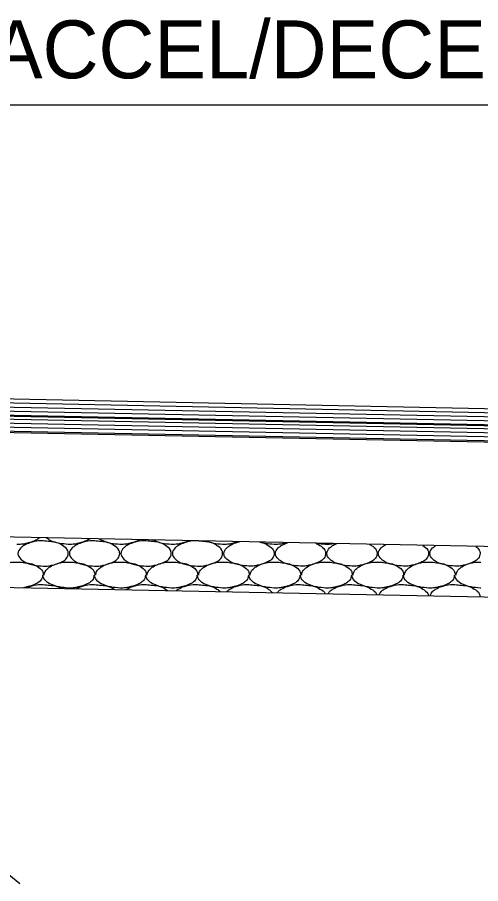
# Model space of a CAD drawing. Extents: x 1364961 to 1365294, y 367927 to 368034.
# Drawn here: x 1365220.25 to 1365224.86, y 367967.31 to 367975.93 of the extents above; entities that cross this region are included whole.
import ezdxf

# ---------------------------------------------------------------- set-up
doc = ezdxf.new("R2010")
doc.units = 0
doc.layers.add('Default', color=7, linetype='Continuous')

msp = doc.modelspace()

# ---------------------------------------------------------------- linework, layer by layer
at = {"layer": 'Default'}
for p, q in [((1365217.487, 367975.0585), (1365229.476, 367975.0585)), ((1365229.476, 367971.9458), (1365193.4981, 367972.6644)), ((1365229.476, 367971.9058), (1365193.4991, 367972.6244)), ((1365229.476, 367971.8657), (1365193.4991, 367972.5844)), ((1365229.476, 367971.7758), (1365193.2513, 367972.4993)), ((1365229.476, 367971.8257), (1365193.5011, 367972.5444)), ((1365229.476, 367971.7857), (1365193.5011, 367972.5044)), ((1365229.476, 367971.7456), (1365193.5021, 367972.4644)), ((1365229.476, 367971.7056), (1365193.5031, 367972.4244)), ((1365229.476, 367971.6126), (1365193.4981, 367972.3314)), ((1365229.476, 367971.6656), (1365193.5031, 367972.3844)), ((1365229.476, 367971.6256), (1365193.5051, 367972.3444)), ((1365232.8432, 367970.506), (1365217.471, 367970.8134)), ((1365220.2539, 367970.6874), (1365220.2479, 367970.6874)), ((1365220.7659, 367970.6874), (1365220.7599, 367970.6874)), ((1365221.2779, 367970.6874), (1365221.2719, 367970.6874)), ((1365221.7899, 367970.6874), (1365221.7839, 367970.6874)), ((1365222.3019, 367970.6874), (1365222.2959, 367970.6874)), ((1365222.8139, 367970.6874), (1365222.8079, 367970.6874)), ((1365223.3259, 367970.6874), (1365223.3199, 367970.6874)), ((1365247.5384, 367969.7092), (1365218.479, 367970.2901)), ((1365220.7659, 367970.2534), (1365220.7599, 367970.2534)), ((1365221.2779, 367970.2534), (1365221.2719, 367970.2534)), ((1365221.7899, 367970.2534), (1365221.7839, 367970.2534)), ((1365222.3019, 367970.2534), (1365222.2959, 367970.2534)), ((1365222.8139, 367970.2534), (1365222.8079, 367970.2534)), ((1365223.3259, 367970.2534), (1365223.3199, 367970.2534)), ((1365223.8379, 367970.2534), (1365223.8319, 367970.2534)), ((1365224.3499, 367970.2534), (1365224.3439, 367970.2534)), ((1365224.8619, 367970.2534), (1365224.8559, 367970.2534)), ((1365220.2803, 367967.3121), (1365218.1228, 367969.0246))]:
    msp.add_line(p, q, dxfattribs=at)
for points in [[(1365220.4769, 367970.7534), (1365220.4479, 367970.7334), (1365220.4079, 367970.7154), (1365220.3479, 367970.6974), (1365220.3099, 367970.6894), (1365220.2539, 367970.6874)], [(1365220.7599, 367970.6874), (1365220.6719, 367970.6974), (1365220.5699, 367970.7334), (1365220.5429, 367970.7524)], [(1365220.5099, 367970.4714), (1365220.4219, 367970.4814), (1365220.3199, 367970.5174), (1365220.2679, 367970.5674), (1365220.2599, 367970.5974), (1365220.2879, 367970.6514), (1365220.3179, 367970.6754), (1365220.3799, 367970.7034), (1365220.4659, 367970.7214), (1365220.5099, 367970.7214), (1365220.5759, 367970.7154), (1365220.6479, 367970.7034), (1365220.7019, 367970.6774), (1365220.7519, 367970.6314), (1365220.7599, 367970.5974), (1365220.7439, 367970.5494), (1365220.7039, 367970.5174), (1365220.6639, 367970.4994), (1365220.6039, 367970.4814), (1365220.5659, 367970.4734), (1365220.5099, 367970.4714)], [(1365220.9769, 367970.7434), (1365220.9599, 367970.7334), (1365220.9199, 367970.7154), (1365220.8599, 367970.6974), (1365220.8219, 367970.6894), (1365220.7659, 367970.6874)], [(1365221.0219, 367970.4714), (1365220.9339, 367970.4814), (1365220.8319, 367970.5174), (1365220.7799, 367970.5674), (1365220.7719, 367970.5974), (1365220.7999, 367970.6514), (1365220.8299, 367970.6754), (1365220.8919, 367970.7034), (1365220.9779, 367970.7214), (1365221.0219, 367970.7214), (1365221.0879, 367970.7154), (1365221.1599, 367970.7034), (1365221.2139, 367970.6774), (1365221.2639, 367970.6314), (1365221.2719, 367970.5974), (1365221.2559, 367970.5494), (1365221.2159, 367970.5174), (1365221.1759, 367970.4994), (1365221.1159, 367970.4814), (1365221.0779, 367970.4734), (1365221.0219, 367970.4714)], [(1365221.2719, 367970.6874), (1365221.1839, 367970.6974), (1365221.0819, 367970.7334), (1365221.0679, 367970.7414)], [(1365221.4719, 367970.7334), (1365221.4319, 367970.7154), (1365221.3719, 367970.6974), (1365221.3339, 367970.6894), (1365221.2779, 367970.6874)], [(1365221.5339, 367970.4714), (1365221.4459, 367970.4814), (1365221.3439, 367970.5174), (1365221.2919, 367970.5674), (1365221.2839, 367970.5974), (1365221.3119, 367970.6514), (1365221.3419, 367970.6754), (1365221.4039, 367970.7034), (1365221.4899, 367970.7214), (1365221.5339, 367970.7214), (1365221.5999, 367970.7154), (1365221.6719, 367970.7034), (1365221.7259, 367970.6774), (1365221.7759, 367970.6314), (1365221.7839, 367970.5974), (1365221.7679, 367970.5494), (1365221.7279, 367970.5174), (1365221.6879, 367970.4994), (1365221.6279, 367970.4814), (1365221.5899, 367970.4734), (1365221.5339, 367970.4714)], [(1365221.7839, 367970.6874), (1365221.6959, 367970.6974), (1365221.5989, 367970.7314)], [(1365221.9639, 367970.7234), (1365221.9439, 367970.7154), (1365221.8839, 367970.6974), (1365221.8459, 367970.6894), (1365221.7899, 367970.6874)], [(1365222.0459, 367970.4714), (1365221.9579, 367970.4814), (1365221.8559, 367970.5174), (1365221.8039, 367970.5674), (1365221.7959, 367970.5974), (1365221.8239, 367970.6514), (1365221.8539, 367970.6754), (1365221.9159, 367970.7034), (1365222.0019, 367970.7214), (1365222.0459, 367970.7214), (1365222.1119, 367970.7154), (1365222.1839, 367970.7034), (1365222.2379, 367970.6774), (1365222.2879, 367970.6314), (1365222.2959, 367970.5974), (1365222.2799, 367970.5494), (1365222.2399, 367970.5174), (1365222.1999, 367970.4994), (1365222.1399, 367970.4814), (1365222.1019, 367970.4734), (1365222.0459, 367970.4714)], [(1365222.2959, 367970.6874), (1365222.2079, 367970.6974), (1365222.1329, 367970.7204)], [(1365222.4519, 367970.7134), (1365222.3959, 367970.6974), (1365222.3579, 367970.6894), (1365222.3019, 367970.6874)], [(1365222.5579, 367970.4714), (1365222.4699, 367970.4814), (1365222.3679, 367970.5174), (1365222.3159, 367970.5674), (1365222.3079, 367970.5974), (1365222.3359, 367970.6514), (1365222.3659, 367970.6754), (1365222.4279, 367970.7034), (1365222.4639, 367970.7134)], [(1365222.6649, 367970.7094), (1365222.6959, 367970.7034), (1365222.7499, 367970.6774), (1365222.7999, 367970.6314), (1365222.8079, 367970.5974), (1365222.7919, 367970.5494), (1365222.7519, 367970.5174), (1365222.7119, 367970.4994), (1365222.6519, 367970.4814), (1365222.6139, 367970.4734), (1365222.5579, 367970.4714)], [(1365222.8079, 367970.6874), (1365222.7199, 367970.6974), (1365222.6739, 367970.7094)], [(1365222.9329, 367970.7044), (1365222.9079, 367970.6974), (1365222.8699, 367970.6894), (1365222.8139, 367970.6874)], [(1365223.0699, 367970.4714), (1365222.9819, 367970.4814), (1365222.8799, 367970.5174), (1365222.8279, 367970.5674), (1365222.8199, 367970.5974), (1365222.8479, 367970.6514), (1365222.8779, 367970.6754), (1365222.9399, 367970.7034), (1365222.9419, 367970.7044)], [(1365223.2239, 367970.6984), (1365223.2619, 367970.6774), (1365223.3119, 367970.6314), (1365223.3199, 367970.5974), (1365223.3039, 367970.5494), (1365223.2639, 367970.5174), (1365223.2239, 367970.4994), (1365223.1639, 367970.4814), (1365223.1259, 367970.4734), (1365223.0699, 367970.4714)], [(1365223.3199, 367970.6874), (1365223.2319, 367970.6974), (1365223.2269, 367970.6984)], [(1365223.4089, 367970.6944), (1365223.3819, 367970.6894), (1365223.3259, 367970.6874)], [(1365223.5819, 367970.4714), (1365223.4939, 367970.4814), (1365223.3919, 367970.5174), (1365223.3399, 367970.5674), (1365223.3319, 367970.5974), (1365223.3599, 367970.6514), (1365223.3899, 367970.6754), (1365223.4279, 367970.6944)], [(1365223.7569, 367970.6874), (1365223.7739, 367970.6774), (1365223.8239, 367970.6314), (1365223.8319, 367970.5974), (1365223.8159, 367970.5494), (1365223.7759, 367970.5174), (1365223.7359, 367970.4994), (1365223.6759, 367970.4814), (1365223.6379, 367970.4734), (1365223.5819, 367970.4714)], [(1365224.0939, 367970.4714), (1365224.0059, 367970.4814), (1365223.9039, 367970.5174), (1365223.8519, 367970.5674), (1365223.8439, 367970.5974), (1365223.8719, 367970.6514), (1365223.9019, 367970.6754), (1365223.9189, 367970.6844)], [(1365224.2859, 367970.6774), (1365224.3359, 367970.6314), (1365224.3439, 367970.5974), (1365224.3279, 367970.5494), (1365224.2879, 367970.5174), (1365224.2479, 367970.4994), (1365224.1879, 367970.4814), (1365224.1499, 367970.4734), (1365224.0939, 367970.4714)], [(1365224.6059, 367970.4714), (1365224.5179, 367970.4814), (1365224.4159, 367970.5174), (1365224.3639, 367970.5674), (1365224.3559, 367970.5974), (1365224.3839, 367970.6514), (1365224.4129, 367970.6744)], [(1365224.8139, 367970.6664), (1365224.8479, 367970.6314), (1365224.8559, 367970.5974), (1365224.8399, 367970.5494), (1365224.7999, 367970.5174), (1365224.7599, 367970.4994), (1365224.6999, 367970.4814), (1365224.6619, 367970.4734), (1365224.6059, 367970.4714)], [(1365220.0099, 367970.3814), (1365220.0099, 367970.3874), (1365220.0379, 367970.4414), (1365220.0679, 367970.4654), (1365220.1299, 367970.4934), (1365220.2159, 367970.5114), (1365220.2539, 367970.5114)], [(1365220.2539, 367970.5114), (1365220.2619, 367970.5114), (1365220.3279, 367970.5054), (1365220.3999, 367970.4934), (1365220.4539, 367970.4674), (1365220.5039, 367970.4214), (1365220.5119, 367970.3874), (1365220.5119, 367970.3814)], [(1365220.5219, 367970.3814), (1365220.5219, 367970.3874), (1365220.5499, 367970.4414), (1365220.5799, 367970.4654), (1365220.6419, 367970.4934), (1365220.7279, 367970.5114), (1365220.7659, 367970.5114)], [(1365220.7659, 367970.5114), (1365220.7739, 367970.5114), (1365220.8399, 367970.5054), (1365220.9119, 367970.4934), (1365220.9659, 367970.4674), (1365221.0159, 367970.4214), (1365221.0239, 367970.3874), (1365221.0239, 367970.3814)], [(1365221.0339, 367970.3814), (1365221.0339, 367970.3874), (1365221.0619, 367970.4414), (1365221.0919, 367970.4654), (1365221.1539, 367970.4934), (1365221.2399, 367970.5114), (1365221.2779, 367970.5114)], [(1365221.2779, 367970.5114), (1365221.2859, 367970.5114), (1365221.3519, 367970.5054), (1365221.4239, 367970.4934), (1365221.4779, 367970.4674), (1365221.5279, 367970.4214), (1365221.5359, 367970.3874), (1365221.5359, 367970.3814)], [(1365221.5459, 367970.3814), (1365221.5459, 367970.3874), (1365221.5739, 367970.4414), (1365221.6039, 367970.4654), (1365221.6659, 367970.4934), (1365221.7519, 367970.5114), (1365221.7899, 367970.5114)], [(1365221.7899, 367970.5114), (1365221.7979, 367970.5114), (1365221.8639, 367970.5054), (1365221.9359, 367970.4934), (1365221.9899, 367970.4674), (1365222.0399, 367970.4214), (1365222.0479, 367970.3874), (1365222.0479, 367970.3814)], [(1365222.0579, 367970.3814), (1365222.0579, 367970.3874), (1365222.0859, 367970.4414), (1365222.1159, 367970.4654), (1365222.1779, 367970.4934), (1365222.2639, 367970.5114), (1365222.3019, 367970.5114)], [(1365222.3019, 367970.5114), (1365222.3099, 367970.5114), (1365222.3759, 367970.5054), (1365222.4479, 367970.4934), (1365222.5019, 367970.4674), (1365222.5519, 367970.4214), (1365222.5599, 367970.3874), (1365222.5599, 367970.3814)], [(1365222.5699, 367970.3814), (1365222.5699, 367970.3874), (1365222.5979, 367970.4414), (1365222.6279, 367970.4654), (1365222.6899, 367970.4934), (1365222.7759, 367970.5114), (1365222.8139, 367970.5114)], [(1365222.8139, 367970.5114), (1365222.8219, 367970.5114), (1365222.8879, 367970.5054), (1365222.9599, 367970.4934), (1365223.0139, 367970.4674), (1365223.0639, 367970.4214), (1365223.0719, 367970.3874), (1365223.0719, 367970.3814)], [(1365223.0819, 367970.3814), (1365223.0819, 367970.3874), (1365223.1099, 367970.4414), (1365223.1399, 367970.4654), (1365223.2019, 367970.4934), (1365223.2879, 367970.5114), (1365223.3259, 367970.5114)], [(1365223.3259, 367970.5114), (1365223.3339, 367970.5114), (1365223.3999, 367970.5054), (1365223.4719, 367970.4934), (1365223.5259, 367970.4674), (1365223.5759, 367970.4214), (1365223.5839, 367970.3874), (1365223.5839, 367970.3814)], [(1365223.5939, 367970.3814), (1365223.5939, 367970.3874), (1365223.6219, 367970.4414), (1365223.6519, 367970.4654), (1365223.7139, 367970.4934), (1365223.7999, 367970.5114), (1365223.8379, 367970.5114)], [(1365223.8379, 367970.5114), (1365223.8459, 367970.5114), (1365223.9119, 367970.5054), (1365223.9839, 367970.4934), (1365224.0379, 367970.4674), (1365224.0879, 367970.4214), (1365224.0959, 367970.3874), (1365224.0959, 367970.3814)], [(1365224.1059, 367970.3814), (1365224.1059, 367970.3874), (1365224.1339, 367970.4414), (1365224.1639, 367970.4654), (1365224.2259, 367970.4934), (1365224.3119, 367970.5114), (1365224.3499, 367970.5114)], [(1365224.3499, 367970.5114), (1365224.3579, 367970.5114), (1365224.4239, 367970.5054), (1365224.4959, 367970.4934), (1365224.5499, 367970.4674), (1365224.5999, 367970.4214), (1365224.6079, 367970.3874), (1365224.6079, 367970.3814)], [(1365224.6179, 367970.3814), (1365224.6179, 367970.3874), (1365224.6459, 367970.4414), (1365224.6759, 367970.4654), (1365224.7379, 367970.4934), (1365224.8239, 367970.5114), (1365224.8619, 367970.5114)], [(1365220.5039, 367970.3814), (1365220.5039, 367970.3794), (1365220.4879, 367970.3314), (1365220.4479, 367970.2994), (1365220.4079, 367970.2814), (1365220.3479, 367970.2634), (1365220.3169, 367970.2564)], [(1365220.7599, 367970.2534), (1365220.6719, 367970.2634), (1365220.5699, 367970.2994), (1365220.5179, 367970.3494), (1365220.5099, 367970.3794), (1365220.5099, 367970.3814)], [(1365221.0159, 367970.3814), (1365221.0159, 367970.3794), (1365220.9999, 367970.3314), (1365220.9599, 367970.2994), (1365220.9199, 367970.2814), (1365220.8599, 367970.2634), (1365220.8219, 367970.2554), (1365220.7659, 367970.2534)], [(1365221.2719, 367970.2534), (1365221.1839, 367970.2634), (1365221.0819, 367970.2994), (1365221.0299, 367970.3494), (1365221.0219, 367970.3794), (1365221.0219, 367970.3814)], [(1365221.5279, 367970.3814), (1365221.5279, 367970.3794), (1365221.5119, 367970.3314), (1365221.4719, 367970.2994), (1365221.4319, 367970.2814), (1365221.3719, 367970.2634), (1365221.3339, 367970.2554), (1365221.2779, 367970.2534)], [(1365221.7839, 367970.2534), (1365221.6959, 367970.2634), (1365221.5939, 367970.2994), (1365221.5419, 367970.3494), (1365221.5339, 367970.3794), (1365221.5339, 367970.3814)], [(1365222.0399, 367970.3814), (1365222.0399, 367970.3794), (1365222.0239, 367970.3314), (1365221.9839, 367970.2994), (1365221.9439, 367970.2814), (1365221.8839, 367970.2634), (1365221.8459, 367970.2554), (1365221.7899, 367970.2534)], [(1365222.2959, 367970.2534), (1365222.2079, 367970.2634), (1365222.1059, 367970.2994), (1365222.0539, 367970.3494), (1365222.0459, 367970.3794), (1365222.0459, 367970.3814)], [(1365222.5519, 367970.3814), (1365222.5519, 367970.3794), (1365222.5359, 367970.3314), (1365222.4959, 367970.2994), (1365222.4559, 367970.2814), (1365222.3959, 367970.2634), (1365222.3579, 367970.2554), (1365222.3019, 367970.2534)], [(1365222.8079, 367970.2534), (1365222.7199, 367970.2634), (1365222.6179, 367970.2994), (1365222.5659, 367970.3494), (1365222.5579, 367970.3794), (1365222.5579, 367970.3814)], [(1365223.0639, 367970.3814), (1365223.0639, 367970.3794), (1365223.0479, 367970.3314), (1365223.0079, 367970.2994), (1365222.9679, 367970.2814), (1365222.9079, 367970.2634), (1365222.8699, 367970.2554), (1365222.8139, 367970.2534)], [(1365223.3199, 367970.2534), (1365223.2319, 367970.2634), (1365223.1299, 367970.2994), (1365223.0779, 367970.3494), (1365223.0699, 367970.3794), (1365223.0699, 367970.3814)], [(1365223.5759, 367970.3814), (1365223.5759, 367970.3794), (1365223.5599, 367970.3314), (1365223.5199, 367970.2994), (1365223.4799, 367970.2814), (1365223.4199, 367970.2634), (1365223.3819, 367970.2554), (1365223.3259, 367970.2534)], [(1365223.8319, 367970.2534), (1365223.7439, 367970.2634), (1365223.6419, 367970.2994), (1365223.5899, 367970.3494), (1365223.5819, 367970.3794), (1365223.5819, 367970.3814)], [(1365224.0879, 367970.3814), (1365224.0879, 367970.3794), (1365224.0719, 367970.3314), (1365224.0319, 367970.2994), (1365223.9919, 367970.2814), (1365223.9319, 367970.2634), (1365223.8939, 367970.2554), (1365223.8379, 367970.2534)], [(1365224.3439, 367970.2534), (1365224.2559, 367970.2634), (1365224.1539, 367970.2994), (1365224.1019, 367970.3494), (1365224.0939, 367970.3794), (1365224.0939, 367970.3814)], [(1365224.5999, 367970.3814), (1365224.5999, 367970.3794), (1365224.5839, 367970.3314), (1365224.5439, 367970.2994), (1365224.5039, 367970.2814), (1365224.4439, 367970.2634), (1365224.4059, 367970.2554), (1365224.3499, 367970.2534)], [(1365224.8559, 367970.2534), (1365224.7679, 367970.2634), (1365224.6659, 367970.2994), (1365224.6139, 367970.3494), (1365224.6059, 367970.3794), (1365224.6059, 367970.3814)], [(1365220.3459, 367970.2564), (1365220.3799, 367970.2694), (1365220.4659, 367970.2874), (1365220.5099, 367970.2874), (1365220.5759, 367970.2814), (1365220.6479, 367970.2694), (1365220.6929, 367970.2494)], [(1365220.8389, 367970.2464), (1365220.8919, 367970.2694), (1365220.9779, 367970.2874), (1365221.0219, 367970.2874), (1365221.0879, 367970.2814), (1365221.1599, 367970.2694), (1365221.2139, 367970.2434), (1365221.2219, 367970.2384)], [(1365221.3339, 367970.2364), (1365221.3419, 367970.2414), (1365221.4039, 367970.2694), (1365221.4899, 367970.2874), (1365221.5339, 367970.2874), (1365221.5999, 367970.2814), (1365221.6719, 367970.2694), (1365221.7259, 367970.2434), (1365221.7479, 367970.2284)], [(1365221.8329, 367970.2264), (1365221.8539, 367970.2414), (1365221.9159, 367970.2694), (1365222.0019, 367970.2874), (1365222.0459, 367970.2874), (1365222.1119, 367970.2814), (1365222.1839, 367970.2694), (1365222.2379, 367970.2434), (1365222.2719, 367970.2174)], [(1365222.3349, 367970.2164), (1365222.3359, 367970.2174), (1365222.3659, 367970.2414), (1365222.4279, 367970.2694), (1365222.5139, 367970.2874), (1365222.5579, 367970.2874), (1365222.6239, 367970.2814), (1365222.6959, 367970.2694), (1365222.7499, 367970.2434), (1365222.7929, 367970.2074)], [(1365222.8389, 367970.2064), (1365222.8479, 367970.2174), (1365222.8779, 367970.2414), (1365222.9399, 367970.2694), (1365223.0259, 367970.2874), (1365223.0699, 367970.2874), (1365223.1359, 367970.2814), (1365223.2079, 367970.2694), (1365223.2619, 367970.2434), (1365223.3119, 367970.1974), (1365223.3119, 367970.1964)], [(1365223.3439, 367970.1964), (1365223.3599, 367970.2174), (1365223.3899, 367970.2414), (1365223.4519, 367970.2694), (1365223.5379, 367970.2874), (1365223.5819, 367970.2874), (1365223.6479, 367970.2814), (1365223.7199, 367970.2694), (1365223.7739, 367970.2434), (1365223.8239, 367970.1974), (1365223.8289, 367970.1864)], [(1365223.8509, 367970.1854), (1365223.8719, 367970.2174), (1365223.9019, 367970.2414), (1365223.9639, 367970.2694), (1365224.0499, 367970.2874), (1365224.0939, 367970.2874), (1365224.1599, 367970.2814), (1365224.2319, 367970.2694), (1365224.2859, 367970.2434), (1365224.3359, 367970.1974), (1365224.3439, 367970.1764)], [(1365224.3589, 367970.1754), (1365224.3839, 367970.2174), (1365224.4139, 367970.2414), (1365224.4759, 367970.2694), (1365224.5619, 367970.2874), (1365224.6059, 367970.2874), (1365224.6719, 367970.2814), (1365224.7439, 367970.2694), (1365224.7979, 367970.2434), (1365224.8479, 367970.1974), (1365224.8559, 367970.1654)]]:
    msp.add_spline(points, degree=3, dxfattribs=at)

# ---------------------------------------------------------------- texts
msp.add_text('12\'-0" ACCEL/DECEL LANE', height=0.576, dxfattribs=at).set_placement((1365217.8148, 367975.3238))

doc.saveas('drawing.dxf')
